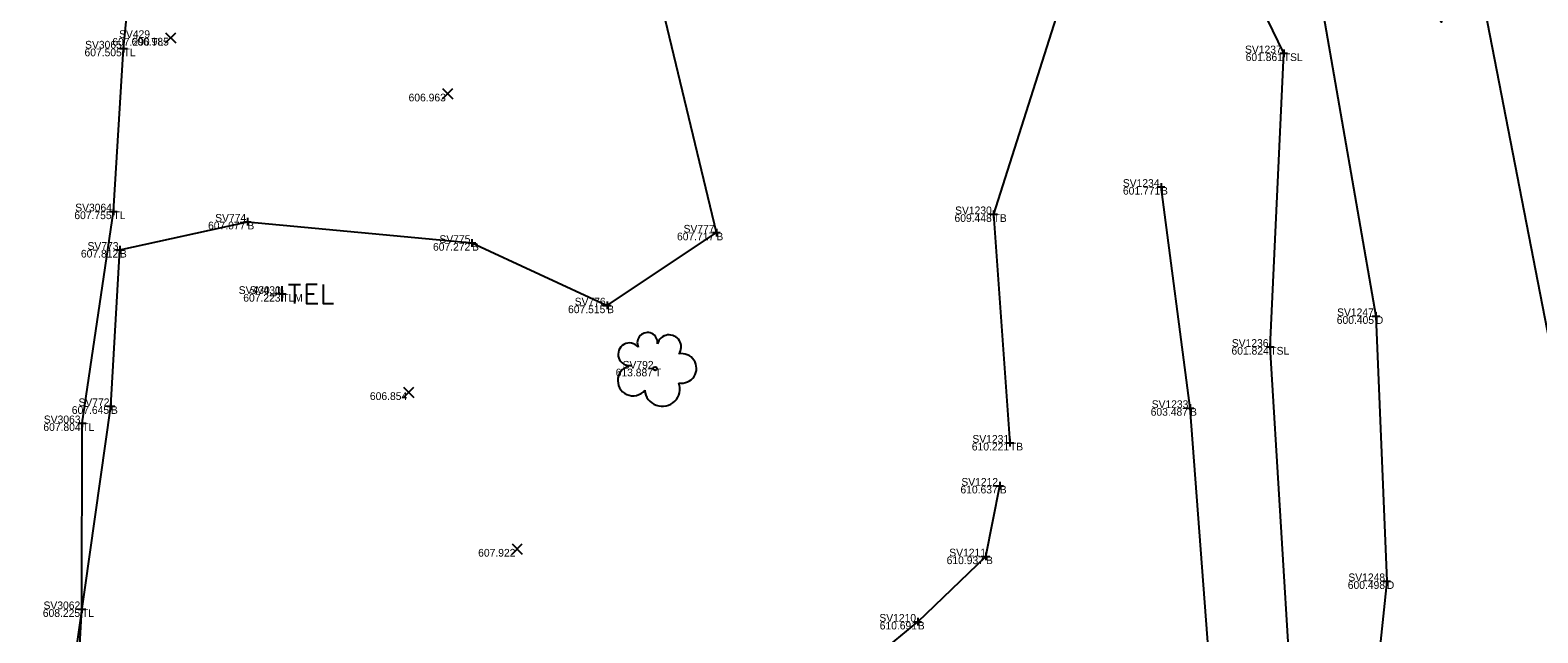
# Model space of a CAD drawing. Extents: x -2 to 1979875, y -2 to 232027.
# Drawn here: x 1978801.8 to 1978899.5, y 231322.8 to 231361.9 of the extents above; entities that cross this region are included whole.
import ezdxf

# ---------------------------------------------------------------- set-up
doc = ezdxf.new("R2010")
doc.units = 0
for name, color, linetype in [('_CIVIL_CONSTRUCTION', 7, 'Continuous'), ('DR_X_Ditch', 7, 'Continuous'), ('GE_P_Alignment', 7, 'Continuous'), ('GE_P_Alignment_1000_Curve_Data', 7, 'Continuous'), ('GE_P_Alignment_100_Stations', 7, 'Continuous'), ('GE_X_Alignment', 7, 'Continuous'), ('GE_X_Alignment_100_Curve_Data', 7, 'Continuous'), ('GE_X_Alignment_100_Stations', 7, 'Continuous'), ('HY_X_Water_Edge', 7, 'Continuous'), ('SV_X_Random_Point', 7, 'Continuous'), ('SV_X_Toe_of_Slope', 7, 'Continuous'), ('SV_X_Top_of_Bank', 7, 'Continuous'), ('VG_X_Cells', 7, 'Continuous')]:
    doc.layers.add(name, color=color, linetype=linetype)

msp = doc.modelspace()

# ---------------------------------------------------------------- linework, layer by layer
at = {"layer": 'DR_X_Ditch'}
msp.add_lwpolyline([(1978869.602, 231440.78), (1978870, 231423.312), (1978870.757, 231401.498), (1978878.811, 231381.318), (1978885.453, 231363.805), (1978889.017, 231343.317), (1978889.726, 231326.131), (1978887.247, 231302.424)], dxfattribs=at)
at = {"layer": 'GE_P_Alignment'}
for points in [[(1978805.078, 231302.902), (1978804.312, 231318.393), (1978807.025, 231337.482), (1978807.608, 231347.62), (1978815.872, 231349.445), (1978830.429, 231348.066), (1978839.191, 231344.012), (1978846.269, 231348.737), (1978841.316, 231369.431), (1978838.009, 231386.763), (1978837.276, 231409.505), (1978850.642, 231428.207)], [(1978878.198, 231321.306), (1978876.972, 231337.361), (1978875.092, 231351.7)], [(1978823.841, 231302.538), (1978835.598, 231310.121), (1978846.229, 231312.385), (1978850.512, 231316.224), (1978859.326, 231323.503), (1978863.746, 231327.737), (1978864.641, 231332.322)]]:
    msp.add_lwpolyline(points, dxfattribs=at)
at = {"layer": 'GE_P_Alignment_1000_Curve_Data'}
msp.add_lwpolyline([(1978800.253, 231250.204), (1978805.284, 231291.391), (1978804.508, 231297.592), (1978804.78, 231306.073), (1978804.463, 231312.372), (1978805.146, 231324.315), (1978805.161, 231336.373), (1978807.189, 231350.111), (1978807.848, 231360.671), (1978809.086, 231373.348), (1978811.125, 231382.982), (1978814.162, 231421.098), (1978816.965, 231468.048), (1978822.427, 231510.515)], dxfattribs=at)
at = {"layer": 'GE_P_Alignment_100_Stations'}
for p, q in [((1978818.128, 231344.759), (1978817.63, 231344.759)), ((1978818.128, 231344.259), (1978818.128, 231345.259))]:
    msp.add_line(p, q, dxfattribs=at)
for points in [[(1978818.536, 231345.38), (1978819.314, 231345.38)], [(1978818.93, 231345.38), (1978818.93, 231344.13)], [(1978820.386, 231345.38), (1978819.707, 231345.38), (1978819.707, 231344.13), (1978820.436, 231344.13)], [(1978819.707, 231344.76), (1978820.19, 231344.76)], [(1978820.78, 231345.38), (1978820.78, 231344.13), (1978821.459, 231344.13)]]:
    msp.add_lwpolyline(points, dxfattribs=at)
at = {"layer": 'GE_X_Alignment_100_Curve_Data'}
for p, q in [((1978807.598, 231360.671), (1978808.098, 231360.671)), ((1978807.848, 231360.921), (1978807.848, 231360.421)), ((1978807.848, 231360.671), (1978807.848, 231360.671)), ((1978883.048, 231360.613), (1978883.048, 231360.113)), ((1978882.798, 231360.363), (1978883.298, 231360.363)), ((1978883.048, 231360.363), (1978883.048, 231360.363)), ((1978874.842, 231351.7), (1978875.342, 231351.7)), ((1978875.092, 231351.95), (1978875.092, 231351.45)), ((1978875.092, 231351.7), (1978875.092, 231351.7)), ((1978806.939, 231350.111), (1978807.439, 231350.111)), ((1978807.189, 231350.361), (1978807.189, 231349.861)), ((1978807.189, 231350.111), (1978807.189, 231350.111)), ((1978815.872, 231349.695), (1978815.872, 231349.195)), ((1978863.985, 231349.929), (1978864.485, 231349.929)), ((1978864.235, 231350.179), (1978864.235, 231349.679)), ((1978864.235, 231349.929), (1978864.235, 231349.929)), ((1978815.622, 231349.445), (1978816.122, 231349.445)), ((1978815.872, 231349.445), (1978815.872, 231349.445)), ((1978846.019, 231348.737), (1978846.519, 231348.737)), ((1978846.269, 231348.987), (1978846.269, 231348.487)), ((1978846.269, 231348.737), (1978846.269, 231348.737)), ((1978807.608, 231347.87), (1978807.608, 231347.37)), ((1978830.179, 231348.066), (1978830.679, 231348.066)), ((1978830.429, 231348.316), (1978830.429, 231347.816)), ((1978830.429, 231348.066), (1978830.429, 231348.066)), ((1978807.358, 231347.62), (1978807.858, 231347.62)), ((1978807.608, 231347.62), (1978807.608, 231347.62)), ((1978817.878, 231344.759), (1978818.378, 231344.759)), ((1978818.128, 231345.009), (1978818.128, 231344.509)), ((1978818.128, 231344.759), (1978818.128, 231344.759)), ((1978838.941, 231344.012), (1978839.441, 231344.012)), ((1978839.191, 231344.262), (1978839.191, 231343.762)), ((1978839.191, 231344.012), (1978839.191, 231344.012)), ((1978888.767, 231343.317), (1978889.267, 231343.317)), ((1978889.017, 231343.567), (1978889.017, 231343.067)), ((1978889.017, 231343.317), (1978889.017, 231343.317)), ((1978881.925, 231341.325), (1978882.425, 231341.325)), ((1978882.175, 231341.575), (1978882.175, 231341.075)), ((1978882.175, 231341.325), (1978882.175, 231341.325)), ((1978806.775, 231337.482), (1978807.275, 231337.482)), ((1978807.025, 231337.732), (1978807.025, 231337.232)), ((1978807.025, 231337.482), (1978807.025, 231337.482)), ((1978876.722, 231337.361), (1978877.222, 231337.361)), ((1978876.972, 231337.611), (1978876.972, 231337.111)), ((1978876.972, 231337.361), (1978876.972, 231337.361)), ((1978804.911, 231336.373), (1978805.411, 231336.373)), ((1978805.161, 231336.623), (1978805.161, 231336.123)), ((1978805.161, 231336.373), (1978805.161, 231336.373)), ((1978865.048, 231335.108), (1978865.548, 231335.108)), ((1978865.298, 231335.358), (1978865.298, 231334.858)), ((1978865.298, 231335.108), (1978865.298, 231335.108)), ((1978864.391, 231332.322), (1978864.891, 231332.322)), ((1978864.641, 231332.572), (1978864.641, 231332.072)), ((1978864.641, 231332.322), (1978864.641, 231332.322)), ((1978863.496, 231327.737), (1978863.996, 231327.737)), ((1978863.746, 231327.987), (1978863.746, 231327.487)), ((1978863.746, 231327.737), (1978863.746, 231327.737)), ((1978889.726, 231326.381), (1978889.726, 231325.881)), ((1978889.476, 231326.131), (1978889.976, 231326.131)), ((1978889.726, 231326.131), (1978889.726, 231326.131)), ((1978804.896, 231324.315), (1978805.396, 231324.315)), ((1978805.146, 231324.565), (1978805.146, 231324.065)), ((1978805.146, 231324.315), (1978805.146, 231324.315)), ((1978859.076, 231323.503), (1978859.576, 231323.503)), ((1978859.326, 231323.753), (1978859.326, 231323.253)), ((1978859.326, 231323.503), (1978859.326, 231323.503))]:
    msp.add_line(p, q, dxfattribs=at)
at = {"layer": 'HY_X_Water_Edge'}
for points in [[(1978903.083, 231327.23), (1978894.356, 231372.194), (1978894.657, 231399.855), (1978884.959, 231411.073), (1978878.075, 231425.727), (1978877.431, 231441.499), (1978876.512, 231460.625), (1978878.349, 231477.303), (1978884.083, 231491.836), (1978891.059, 231500.97), (1978902.062, 231518.216)], [(1978738.528, 231278.008), (1978757.257, 231280.755), (1978763.371, 231281.556), (1978784.159, 231284.036), (1978793.351, 231279.988), (1978807.698, 231286.514), (1978821.562, 231291.295), (1978840.747, 231297.53), (1978857.609, 231304.298), (1978872.974, 231309.553), (1978877.125, 231314.237), (1978883.495, 231319.371), (1978882.175, 231341.325), (1978883.048, 231360.363), (1978875.551, 231375.847), (1978868.903, 231394.228), (1978864.235, 231416.891), (1978862.047, 231444.318), (1978861.234, 231465.995)]]:
    msp.add_lwpolyline(points, dxfattribs=at)
at = {"layer": 'SV_X_Random_Point'}
for p, q in [((1978810.564, 231361.034), (1978811.23, 231361.702)), ((1978810.564, 231361.702), (1978811.23, 231361.034)), ((1978828.511, 231357.411), (1978829.177, 231358.079)), ((1978828.511, 231358.079), (1978829.177, 231357.411)), ((1978825.995, 231338.05), (1978826.661, 231338.718)), ((1978825.995, 231338.718), (1978826.661, 231338.05)), ((1978833.024, 231327.891), (1978833.69, 231328.559)), ((1978833.024, 231328.559), (1978833.69, 231327.891))]:
    msp.add_line(p, q, dxfattribs=at)
at = {"layer": 'SV_X_Toe_of_Slope'}
for points in [[(1978883.495, 231319.371), (1978882.175, 231341.325), (1978883.048, 231360.363), (1978875.551, 231375.847), (1978868.903, 231394.228), (1978864.235, 231416.891), (1978862.314, 231443.891)], [(1978903.083, 231327.23), (1978894.356, 231372.194), (1978893.272, 231362.375), (1978887.322, 231372.706), (1978881.59, 231392.813), (1978875.638, 231410.655), (1978878.075, 231425.727), (1978877.237, 231441.367)]]:
    msp.add_lwpolyline(points, dxfattribs=at)
at = {"layer": 'SV_X_Top_of_Bank'}
msp.add_lwpolyline([(1978856.663, 231439.772), (1978858.804, 231419.484), (1978860.566, 231402.516), (1978863.543, 231394.822), (1978868.033, 231378.258), (1978870.239, 231368.847), (1978864.235, 231349.929), (1978865.298, 231335.108)], dxfattribs=at)
at = {"layer": 'VG_X_Cells'}
msp.add_circle((1978842.294, 231339.915), 0.12, dxfattribs=at)
for centre, radius, start, end in [((1978841.802, 231341.599), 0.658, 354.0047, 205.97412), ((1978843.207, 231341.33), 0.776, 323.82996, 165.0376), ((1978840.639, 231340.847), 0.735, 39.06254, 279.54124), ((1978844.024, 231339.933), 0.957, 259.14531, 101.45961), ((1978840.867, 231339.141), 0.987, 96.17219, 320.57371), ((1978842.767, 231338.612), 1.142, 184.94757, 19.45715)]:
    msp.add_arc(centre, radius, start, end, dxfattribs=at)

# ---------------------------------------------------------------- texts
at = {"layer": '_CIVIL_CONSTRUCTION'}
for s, p in [('606.985', (1978808.362, 231360.868)), ('607.505', (1978805.313, 231360.171)), ('607.290', (1978807.117, 231360.857)), ('601.861', (1978880.578, 231359.863)), ('606.963', (1978826.319, 231357.245)), ('601.771', (1978872.622, 231351.2)), ('607.755', (1978804.654, 231349.611)), ('609.448', (1978861.705, 231349.429)), ('607.077', (1978813.321, 231348.945)), ('607.717', (1978843.718, 231348.237)), ('607.272', (1978827.901, 231347.566)), ('607.812', (1978805.08, 231347.12)), ('607.223', (1978815.603, 231344.259)), ('607.223', (1978815.603, 231344.259)), ('607.515', (1978836.656, 231343.512)), ('600.405', (1978886.482, 231342.817)), ('601.824', (1978879.659, 231340.825)), ('613.887', (1978839.743, 231339.415)), ('606.854', (1978823.812, 231337.884)), ('607.645', (1978804.49, 231336.982)), ('603.487', (1978874.421, 231336.861)), ('607.804', (1978802.645, 231335.873)), ('610.221', (1978862.828, 231334.608)), ('610.637', (1978862.09, 231331.822)), ('607.922', (1978830.829, 231327.725)), ('610.937', (1978861.195, 231327.237)), ('600.498', (1978887.196, 231325.631)), ('608.225', (1978802.611, 231323.815)), ('610.691', (1978856.856, 231323.003))]:
    msp.add_text(s, height=0.5, dxfattribs=at).set_placement(p)
at = {"layer": 'GE_X_Alignment'}
for s, p in [('SV429', (1978807.553, 231361.357)), ('SV3065', (1978805.351, 231360.671)), ('SV1237', (1978880.535, 231360.363)), ('SV1234', (1978872.615, 231351.7)), ('SV3064', (1978804.712, 231350.111)), ('SV774', (1978813.783, 231349.445)), ('SV1230', (1978861.743, 231349.929)), ('SV777', (1978844.144, 231348.737)), ('SV773', (1978805.51, 231347.62)), ('SV775', (1978828.32, 231348.066)), ('SV430_1', (1978815.308, 231344.759)), ('SV430', (1978816.024, 231344.759)), ('SV776', (1978837.086, 231344.012)), ('SV1247', (1978886.504, 231343.317)), ('SV1236', (1978879.681, 231341.325)), ('SV792', (1978840.193, 231339.915)), ('SV772', (1978804.924, 231337.482)), ('SV1233', (1978874.486, 231337.361)), ('SV3063', (1978802.675, 231336.373)), ('SV1231', (1978862.866, 231335.108)), ('SV1212', (1978862.151, 231332.322)), ('SV1211', (1978861.366, 231327.737)), ('SV1248', (1978887.235, 231326.131)), ('SV3062', (1978802.656, 231324.315)), ('SV1210', (1978856.834, 231323.503))]:
    msp.add_text(s, height=0.5, dxfattribs=at).set_placement(p)
at = {"layer": 'GE_X_Alignment_100_Stations'}
for s, p in [('TL', (1978807.848, 231360.171)), ('TL', (1978809.647, 231360.857)), ('TSL', (1978883.048, 231359.863)), ('B', (1978875.092, 231351.2)), ('TL', (1978807.189, 231349.611)), ('TB', (1978864.235, 231349.429)), ('B', (1978815.872, 231348.945)), ('B', (1978846.269, 231348.237)), ('B', (1978830.429, 231347.566)), ('B', (1978807.608, 231347.12)), ('TL', (1978818.128, 231344.259)), ('TLM', (1978818.128, 231344.259)), ('B', (1978839.191, 231343.512)), ('D', (1978889.017, 231342.817)), ('TSL', (1978882.175, 231340.825)), ('T', (1978842.294, 231339.415)), ('B', (1978807.025, 231336.982)), ('B', (1978876.972, 231336.861)), ('TL', (1978805.161, 231335.873)), ('TB', (1978865.298, 231334.608)), ('B', (1978864.641, 231331.822)), ('B', (1978863.746, 231327.237)), ('D', (1978889.726, 231325.631)), ('TL', (1978805.146, 231323.815)), ('B', (1978859.326, 231323.003))]:
    msp.add_text(s, height=0.5, dxfattribs=at).set_placement(p)

doc.saveas('drawing.dxf')
